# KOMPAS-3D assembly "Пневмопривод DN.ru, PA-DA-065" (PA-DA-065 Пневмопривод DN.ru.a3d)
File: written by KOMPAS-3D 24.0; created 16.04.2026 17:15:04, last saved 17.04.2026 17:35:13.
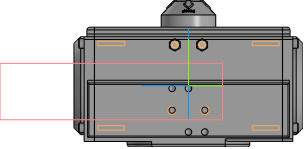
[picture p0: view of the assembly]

Document properties: Автор: DN.ru; Полное имя файла: C:\Работа\PA-DA-х Пневмопривод DN.ru\065\исходные материалы\PA-DA-065 Пневмопривод DN.ru.a3d

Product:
- Component [detail]: Пневмопривод DN.ru  | designation PA-DA-065  | qty 1  | pos. 1  | Масса: 2; Раздел спецификации: Прочие изделия; Примечание: D290-00294; Автор: DN.ru; source file: PA-DA-065 Пневмопривод DN.ru.m3d
- Component [standard]: Винт М4-6gx30 ГОСТ 11738-84  | qty 8  | Масса: 0.00361; Раздел спецификации: Стандартные изделия; Рассекать на разрезах: no
- Component [standard]: Болт М5-6gx50 ГОСТ 7805-70  | qty 2  | Масса: 0.008999; Раздел спецификации: Стандартные изделия; Рассекать на разрезах: no
- Component [standard]: Гайка М5-6H ГОСТ 5915-70  | qty 2  | Масса: 0.00144; Раздел спецификации: Стандартные изделия; Рассекать на разрезах: no
- Part/product: Пневмопривод DN.ru  | designation PA-DA-065
    Масса: 2
    Раздел спецификации: Прочие изделия
    Примечание: D290-00294

Expressions: D290-00293; D290-00294
Referenced files in C:\Работа\PA-DA-х Пневмопривод DN.ru\052\исходные материалы\: PA-DA-052 Пневмопривод DN.ru.m3d
Referenced files in C:\Работа\PA-DA-х Пневмопривод DN.ru\065\исходные материалы\: PA-DA-065 Пневмопривод DN.ru.m3d
Referenced files in C:\Program Files\ASCON\KOMPAS-3D v24\Libs\PolynomLib\DATA\vault\Methods\Kompas\3D\: PLib_Screw_GOST_11738_1500.m3d, PLib_Bolt_1_900.m3d, PLib_Nut_OST92_900.m3d
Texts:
  PA-DA-052
  Крепежное изделие ГОСТ
  BOSimple***PART:1ff84fa3-e62c-5a6d-126f-35e3f1af4542***SHORTLOC:Root±30±20±10±80±10±GMC90[Нет;Без покрытия;Без указания материала;0,7;-;30;4]
  BOSimple***PART:53acba15-081d-1c02-6810-072b309dd366***SHORTLOC:Root±30±20±10±80±10±©{}30±©{BASE}130±30[Нет;Без покрытия;Без указания материала;50;5;8;0,8;-]
  BOSimple***PART:0338bb82-6b79-df62-da33-8b23172f1b3e***SHORTLOC:Root±30±10±20±©{}110±10±50±60[Нет;Без покрытия;Без указания материала;-;5;0,8;8]
  Программные изделия  и базы данных
  PA-DA-065
  PA-DA-065  Пневмопривод DN.ru
  Винт М4-6gx30 ГОСТ 11738-84 (1)
  Винт М4-6gx30 ГОСТ 11738-84 (2)
  Винт М4-6gx30 ГОСТ 11738-84 (3)
  Винт М4-6gx30 ГОСТ 11738-84 (4)
  Винт М4-6gx30 ГОСТ 11738-84 (5)
  Винт М4-6gx30 ГОСТ 11738-84 (6)
  Винт М4-6gx30 ГОСТ 11738-84 (7)
  Винт М4-6gx30 ГОСТ 11738-84 (8)
  Болт М5-6gx50 ГОСТ 7805-70 (1)
  hole1
  hole2
  Болт М5-6gx50 ГОСТ 7805-70 (2)
  Гайка М5-6H ГОСТ 5915-70 (1)
  bcut1
  hcut1
  cut1
  Гайка М5-6H ГОСТ 5915-70 (2)
  Plane. Начало координат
